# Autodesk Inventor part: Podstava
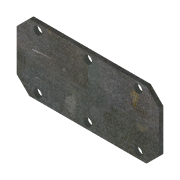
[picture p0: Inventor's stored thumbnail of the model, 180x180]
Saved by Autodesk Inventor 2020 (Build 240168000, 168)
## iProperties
Created: 2025-03
Part Number: Podstava
Material: Ocel
Document SubType Name: Modeling
Designer: doma
Density: 7.85 g/cm^3
Appearance: Plech
Mass: 560.441 g
Surface Area: 320.243 cm^2
Volume: 71.3938 cm^3
Author: doma
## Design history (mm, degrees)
sketch "Náčrt1"
  geometry: L1 (-85, -40)-(85, -40); L2 (85, -40)-(85, 40); L3 (85, 40)-(-85, 40); L4 (-85, 40)-(-85, -40); L5 (-85, -40)-(85, 40); L6 (85, -40)-(-85, 40); L7 (60, 33.5)-(-85, 33.5); L8 (-85, 0)-(-153.032, 0); C1 r 5 at (60, 33.5); C2 r 5 at (0, 33.5); C3 r 5 at (-60, 33.5); C4 r 5 at (-60, -33.5); C5 r 5 at (0, -33.5); C6 r 5 at (60, -33.5); 1 further point
  constraints: 16 end point, 6 centre point, 3 midpoint, 3 point on line, 3 symmetric about line, 2 horizontal, 2 parallel, 2 perpendicular, 3 other
  dimensions: "d0" = 170 distance of L3.end L2.end; "d1" = 80 distance of L2.end L1.end; "d5" = 10 diameter of C1; "d7" = 10 diameter of C2; "d8" = 10 diameter of C3; "d9" = 60 distance of L7.start C2.centre; "d11" = 33.5 vertical distance of point (0, 0) L7.start; "d17" = 60 distance of C2.centre C3.centre; "d18" = 25 distance from line of L2 L7.start
extrude "Vysunutí1" new body sketch "Náčrt1" distance "d12" = 5; taper "d13" = 0 deg
chamfer "Zkosení1" distance "d14" = 15; stored, may be unused: second distance "d15" = 2, angle "d16" = 45 deg
node "Těleso1"
